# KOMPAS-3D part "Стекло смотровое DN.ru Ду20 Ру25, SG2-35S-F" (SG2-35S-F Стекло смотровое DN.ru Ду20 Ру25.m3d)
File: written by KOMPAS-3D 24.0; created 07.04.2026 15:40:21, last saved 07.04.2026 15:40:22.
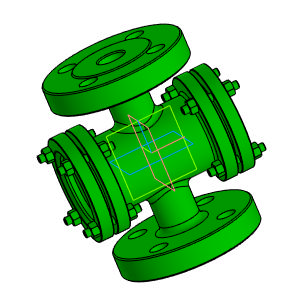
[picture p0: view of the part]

Document properties: Автор: Main; Полное имя файла: D:\DN.ru Аутсерс\Стекло смотровое DN.ru\SG2-35S-F Стекло смотровое DN.ru Ду20 Ру25\SG2-35S-F Стекло смотровое DN.ru Ду20 Ру25.m3d

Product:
- Body: Тело 1  | qty 1
    Масса: 3.869459
- Part/product: Стекло смотровое DN.ru Ду20 Ру25  | designation SG2-35S-F
    Масса: 4.8
    Раздел спецификации: Прочие изделия
    Примечание: D500-00092

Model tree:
1. Операция без истории:1

Expressions: SG2-35S-F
